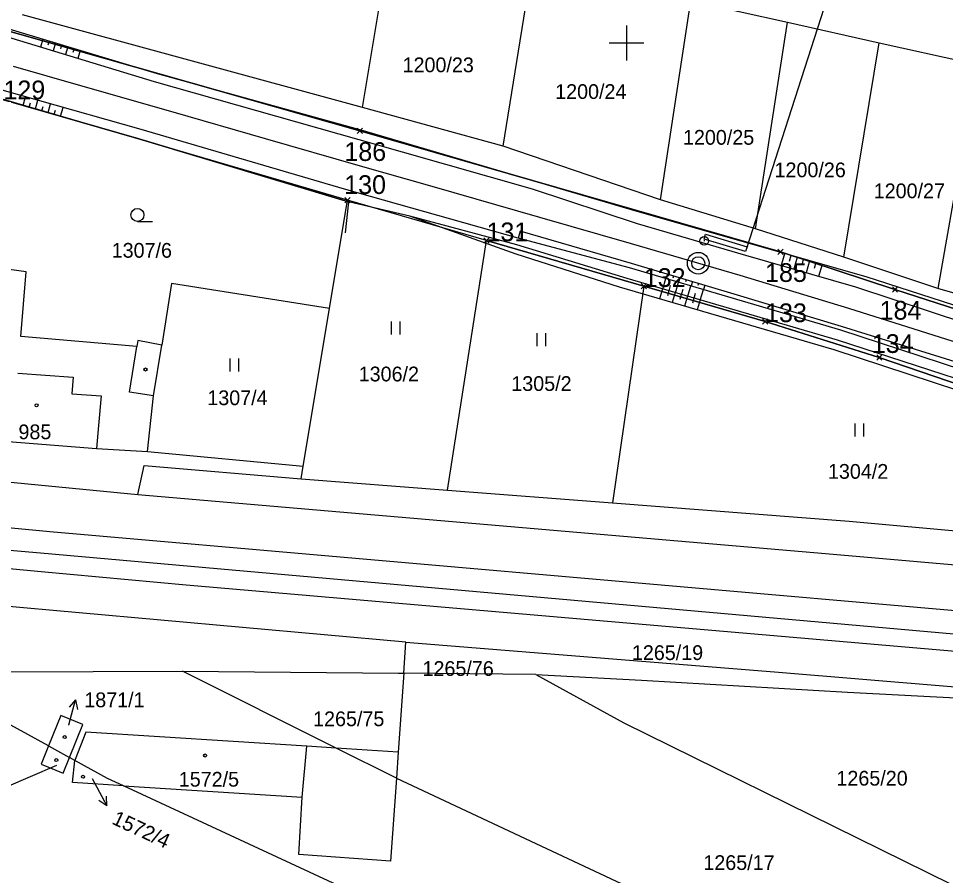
# Model space of a CAD drawing. Extents: x -779302 to -774398, y -1144902 to -1142831.
# Drawn here: x -777170.1 to -777063.2, y -1143896 to -1143797.2 of the extents above; entities that cross this region are included whole.
import ezdxf

# ---------------------------------------------------------------- set-up
doc = ezdxf.new("R2010")
doc.units = 0
for name, color, linetype in [('hektosit - Vrstva 5', 7, 'Continuous'), ('Hranice parcel', 7, 'Continuous'), ('legenda I_5_2 - Vrstva 53', 7, 'Continuous'), ('Parcelní čísla', 7, 'Continuous'), ('Pop  PČ popisy', 7, 'Continuous'), ('SŽDC', 7, 'Continuous'), ('Vnitřní kresba', 7, 'Continuous'), ('zjednodus_g_situ-seda - Vrstva 1', 7, 'Continuous'), ('zjednodus_g_situ-seda - Vrstva 17', 7, 'Continuous'), ('zjednodus_g_situ-seda - Vrstva 48', 7, 'Continuous'), ('zjednodus_g_situ-seda - Vrstva 49', 7, 'Continuous'), ('zjednodus_g_situ-seda - Vrstva 7', 7, 'Continuous'), ('zjednodus_g_situ-seda - Vrstva 9', 7, 'Continuous'), ('Značky budov', 7, 'Continuous'), ('Značky kultur', 7, 'Continuous')]:
    doc.layers.add(name, color=color, linetype=linetype)

msp = doc.modelspace()

# ---------------------------------------------------------------- linework, layer by layer
at = {"layer": 'hektosit - Vrstva 5'}
for p, q in [((-777100, -1143798), (-777100, -1143802)), ((-777102, -1143800), (-777098, -1143800))]:
    msp.add_line(p, q, dxfattribs=at)
at = {"layer": 'Hranice parcel'}
for p, q in [((-777130.46, -1143807.42), (-777127.12, -1143787.44)), ((-777114.23, -1143811.91), (-777110.85, -1143791.06)), ((-777096.09, -1143818.07), (-777092.58, -1143795.13)), ((-777092.58, -1143795.13), (-777081.42, -1143797.61)), ((-777130.46, -1143807.42), (-777169.67, -1143796.75)), ((-777085.1, -1143821.41), (-777081.42, -1143797.61)), ((-777081.42, -1143797.61), (-777070.84, -1143799.97)), ((-777074.92, -1143824.71), (-777070.84, -1143799.97)), ((-777070.84, -1143799.97), (-777059.57, -1143802.48)), ((-777059.57, -1143802.48), (-777064.09, -1143828.29)), ((-777132.17, -1143818.13), (-777171.85, -1143806.53)), ((-777114.23, -1143811.91), (-777130.46, -1143807.42)), ((-777096.09, -1143818.07), (-777114.23, -1143811.91)), ((-777134.26, -1143830.63), (-777132.17, -1143818.13)), ((-777116.14, -1143822.78), (-777132.17, -1143818.13)), ((-777085.1, -1143821.41), (-777096.09, -1143818.07)), ((-777074.92, -1143824.71), (-777085.1, -1143821.41)), ((-777120.64, -1143851.57), (-777116.14, -1143822.78)), ((-777116.14, -1143822.78), (-777098, -1143828.05)), ((-777064.09, -1143828.29), (-777074.92, -1143824.71)), ((-777098, -1143828.05), (-777101.59, -1143853.04)), ((-777053.74, -1143831.32), (-777064.09, -1143828.29)), ((-777137.29, -1143848.79), (-777134.26, -1143830.63)), ((-777155.25, -1143847.09), (-777137.29, -1143848.79)), ((-777137.5, -1143850.27), (-777137.29, -1143848.79)), ((-777137.5, -1143850.27), (-777120.64, -1143851.57)), ((-777120.64, -1143851.57), (-777101.59, -1143853.04)), ((-777125.43, -1143869.09), (-777184.32, -1143863.79)), ((-777125.68, -1143872.67), (-777125.43, -1143869.09)), ((-777125.43, -1143869.09), (-777124.98, -1143869.13)), ((-777151.21, -1143872.43), (-777126.28, -1143872.66)), ((-777126.28, -1143872.66), (-777125.68, -1143872.67)), ((-777110.44, -1143872.81), (-777125.68, -1143872.67)), ((-777166.67, -1143881.06), (-777164.25, -1143882.39)), ((-777163.6, -1143882.75), (-777164.25, -1143882.39))]:
    msp.add_line(p, q, dxfattribs=at)
for points in [[(-776969.85, -1143863.66), (-776987.47, -1143857.88), (-777014.89, -1143846.57), (-777042.6, -1143836.95), (-777069.03, -1143828.43), (-777082.24, -1143824.08), (-777130.76, -1143810.13), (-777274.26, -1143769.36), (-777322.71, -1143754.8), (-777354.97, -1143745.11)], [(-777153.6, -1143834.83), (-777156.35, -1143834.31), (-777156.46, -1143835), (-777169.83, -1143833.84), (-777169.25, -1143826.39), (-777171.18, -1143826.11), (-777174.72, -1143825.65)], [(-777134.26, -1143830.63), (-777152.46, -1143827.73), (-777153.6, -1143834.83)], [(-777098, -1143828.05), (-777084.01, -1143832.11), (-777070.84, -1143836.27), (-777043.81, -1143845.48)], [(-777313.47, -1143830.96), (-777307.07, -1143834.06), (-777294.79, -1143837.91), (-777291.06, -1143838.91), (-777215.44, -1143846.33), (-777156.34, -1143852.08), (-777155.61, -1143848.73), (-777137.5, -1143850.27)], [(-777155.25, -1143847.09), (-777154.55, -1143840.69), (-777153.6, -1143834.83)], [(-776998.39, -1143882.22), (-777014.02, -1143874.66), (-777035.36, -1143870.54), (-777167.58, -1143858.82), (-777281.88, -1143848.9), (-777289.53, -1143848.43), (-777292.27, -1143847.75), (-777303.16, -1143845.03)], [(-777177.16, -1143845.5), (-777161.12, -1143846.74), (-777155.25, -1143847.09)], [(-777101.59, -1143853.04), (-777074.31, -1143855.14), (-777045.91, -1143857.73)], [(-777211.92, -1143858.84), (-777211.13, -1143856.84), (-777167.5, -1143860.96), (-777150.77, -1143862.48), (-777035.76, -1143872.38), (-777017.82, -1143877.1)], [(-777124.98, -1143869.13), (-777082.45, -1143872.54), (-777032.92, -1143876.65)], [(-777166.67, -1143881.06), (-777182.17, -1143872.56), (-777151.21, -1143872.43)], [(-777126.53, -1143884.78), (-777133.48, -1143881.32), (-777151.21, -1143872.43)], [(-777125.68, -1143872.67), (-777126.32, -1143881.78), (-777126.53, -1143884.78)], [(-777110.44, -1143872.81), (-777100.29, -1143878.41), (-777041.02, -1143907.6)], [(-777110.44, -1143872.81), (-777098.28, -1143873.49), (-777074.51, -1143874.84), (-777060.56, -1143875.59), (-777043.14, -1143876.21)], [(-777164.25, -1143882.39), (-777162.69, -1143878.57), (-777165.23, -1143877.53), (-777166.67, -1143881.06)], [(-777158.02, -1143885.65), (-777137.41, -1143886.96), (-777136.87, -1143881.1), (-777162.34, -1143879.46), (-777163.59, -1143882.64), (-777163.6, -1143882.75)], [(-777166.67, -1143881.06), (-777167.52, -1143883.15), (-777164.98, -1143884.18), (-777164.25, -1143882.39)], [(-777158.02, -1143885.65), (-777163.88, -1143885.28), (-777163.6, -1143882.75)], [(-777158.02, -1143885.65), (-777159.84, -1143884.81), (-777163.6, -1143882.75)], [(-777126.53, -1143884.78), (-777059.22, -1143916.33), (-777057.27, -1143917.26)], [(-777064.63, -1143929.09), (-777108.64, -1143908.55), (-777158.02, -1143885.65)]]:
    msp.add_lwpolyline(points, dxfattribs=at)
at = {"layer": 'legenda I_5_2 - Vrstva 53'}
for points in [[(-777442.54, -1143720.48), (-777400.53, -1143733.41), (-777370.73, -1143741.3), (-777366.62, -1143741.88), (-777364.22, -1143742.54), (-777360.64, -1143743.54), (-777354.97, -1143745.11), (-777322.71, -1143754.8), (-777274.26, -1143769.36), (-777130.76, -1143810.13), (-777082.24, -1143824.08), (-777069.03, -1143828.43), (-777042.6, -1143836.95), (-777014.89, -1143846.57), (-776987.47, -1143857.88), (-776969.85, -1143863.66), (-776958.69, -1143867.83), (-776937.4, -1143878.07), (-776932.26, -1143880.54), (-776911.85, -1143884.6)], [(-776982.48, -1143870.69), (-777002.25, -1143861.05), (-777016.74, -1143855.53), (-777043.81, -1143845.48), (-777070.84, -1143836.27), (-777084.01, -1143832.11), (-777098, -1143828.05), (-777116.14, -1143822.78), (-777132.17, -1143818.13), (-777171.85, -1143806.53)]]:
    msp.add_lwpolyline(points, dxfattribs=at)
at = {"layer": 'Pop  PČ popisy'}
for p, q in [((-777164.31, -1143878.64), (-777163.53, -1143875.74)), ((-777163.53, -1143875.74), (-777164.28, -1143876.58)), ((-777163.53, -1143875.74), (-777163.31, -1143876.84)), ((-777164.32, -1143878.66), (-777164.31, -1143878.64)), ((-777165.75, -1143883.32), (-777168.78, -1143884.63)), ((-777168.78, -1143884.63), (-777171.54, -1143885.8)), ((-777161.62, -1143884.81), (-777161.34, -1143885.33)), ((-777161.34, -1143885.33), (-777159.93, -1143887.98)), ((-777159.93, -1143887.98), (-777159.96, -1143886.86)), ((-777159.93, -1143887.98), (-777160.84, -1143887.33))]:
    msp.add_line(p, q, dxfattribs=at)
at = {"layer": 'SŽDC'}
for p, q in [((-777130.56, -1143810.33), (-777131.06, -1143809.83)), ((-777130.56, -1143809.93), (-777131.06, -1143810.43)), ((-777130.96, -1143810.33), (-777130.46, -1143809.83)), ((-777130.96, -1143809.93), (-777130.46, -1143810.43)), ((-777130.76, -1143810.13), (-777130.76, -1143810.13)), ((-777131.97, -1143818.33), (-777132.47, -1143817.83)), ((-777131.97, -1143817.93), (-777132.47, -1143818.43)), ((-777132.37, -1143818.33), (-777131.87, -1143817.83)), ((-777132.37, -1143817.93), (-777131.87, -1143818.43)), ((-777132.17, -1143818.13), (-777132.17, -1143818.13)), ((-777115.94, -1143822.98), (-777116.44, -1143822.48)), ((-777115.94, -1143822.58), (-777116.44, -1143823.08)), ((-777116.34, -1143822.98), (-777115.84, -1143822.48)), ((-777116.34, -1143822.58), (-777115.84, -1143823.08)), ((-777116.14, -1143822.78), (-777116.14, -1143822.78)), ((-777082.04, -1143824.28), (-777082.54, -1143823.78)), ((-777082.04, -1143823.88), (-777082.54, -1143824.38)), ((-777082.44, -1143824.28), (-777081.94, -1143823.78)), ((-777082.44, -1143823.88), (-777081.94, -1143824.38)), ((-777082.24, -1143824.08), (-777082.24, -1143824.08)), ((-777097.8, -1143828.25), (-777098.3, -1143827.75)), ((-777097.8, -1143827.85), (-777098.3, -1143828.35)), ((-777098.2, -1143828.25), (-777097.7, -1143827.75)), ((-777098.2, -1143827.85), (-777097.7, -1143828.35)), ((-777098, -1143828.05), (-777098, -1143828.05)), ((-777068.83, -1143828.63), (-777069.33, -1143828.13)), ((-777068.83, -1143828.23), (-777069.33, -1143828.73)), ((-777069.23, -1143828.63), (-777068.73, -1143828.13)), ((-777069.23, -1143828.23), (-777068.73, -1143828.73)), ((-777069.03, -1143828.43), (-777069.03, -1143828.43)), ((-777083.81, -1143832.31), (-777084.31, -1143831.81)), ((-777083.81, -1143831.91), (-777084.31, -1143832.41)), ((-777084.21, -1143832.31), (-777083.71, -1143831.81)), ((-777084.21, -1143831.91), (-777083.71, -1143832.41)), ((-777084.01, -1143832.11), (-777084.01, -1143832.11)), ((-777070.64, -1143836.47), (-777071.14, -1143835.97)), ((-777071.04, -1143836.47), (-777070.54, -1143835.97)), ((-777070.64, -1143836.07), (-777071.14, -1143836.57)), ((-777071.04, -1143836.07), (-777070.54, -1143836.57)), ((-777070.84, -1143836.27), (-777070.84, -1143836.27))]:
    msp.add_line(p, q, dxfattribs=at)
for points in [[(-777442.54, -1143720.48), (-777400.53, -1143733.41), (-777370.73, -1143741.3), (-777366.62, -1143741.88), (-777364.22, -1143742.54), (-777360.64, -1143743.54), (-777354.97, -1143745.11), (-777322.71, -1143754.8), (-777274.26, -1143769.36), (-777130.76, -1143810.13), (-777082.24, -1143824.08), (-777069.03, -1143828.43), (-777042.6, -1143836.95), (-777014.89, -1143846.57), (-776987.47, -1143857.88), (-776969.85, -1143863.66), (-776958.69, -1143867.83), (-776937.4, -1143878.07), (-776932.26, -1143880.54), (-776911.85, -1143884.6)], [(-776982.48, -1143870.69), (-777002.25, -1143861.05), (-777016.74, -1143855.53), (-777043.81, -1143845.48), (-777070.84, -1143836.27), (-777084.01, -1143832.11), (-777098, -1143828.05), (-777116.14, -1143822.78), (-777132.17, -1143818.13), (-777171.85, -1143806.53)]]:
    msp.add_lwpolyline(points, dxfattribs=at)
at = {"layer": 'Vnitřní kresba'}
for p, q in [((-777157.31, -1143840.25), (-777156.46, -1143835)), ((-777170.21, -1143838.07), (-777163.81, -1143838.54)), ((-777163.81, -1143838.54), (-777163.95, -1143840.45)), ((-777154.55, -1143840.69), (-777157.31, -1143840.25)), ((-777163.95, -1143840.45), (-777160.6, -1143840.7)), ((-777160.6, -1143840.7), (-777160.89, -1143844.1)), ((-777160.89, -1143844.1), (-777161.12, -1143846.74)), ((-777166.52, -1143856.36), (-777216.02, -1143851.57)), ((-777156.34, -1143852.08), (-777077.05, -1143858.86)), ((-777051.48, -1143866.41), (-777166.52, -1143856.36)), ((-777077.05, -1143858.86), (-777046.53, -1143861.57)), ((-777133.48, -1143881.32), (-777136.87, -1143881.1)), ((-777126.32, -1143881.78), (-777133.48, -1143881.32)), ((-777126.53, -1143884.78), (-777127.2, -1143894.33)), ((-777137.77, -1143893.58), (-777137.41, -1143886.96)), ((-777127.2, -1143894.33), (-777137.77, -1143893.58))]:
    msp.add_line(p, q, dxfattribs=at)
at = {"layer": 'zjednodus_g_situ-seda - Vrstva 1'}
msp.add_line((-777122.39, -1143816.56), (-777130.69, -1143814.19), dxfattribs=at)
for points in [[(-777130.69, -1143814.19), (-777141.61, -1143811.05), (-777152.26, -1143807.98), (-777162.91, -1143804.93), (-777170.68, -1143802.7)], [(-776976.22, -1143866.7), (-776986.48, -1143862.49), (-776998.36, -1143857.65), (-777010.89, -1143852.7), (-777023.89, -1143847.77), (-777036.16, -1143843.3), (-777048.78, -1143838.91), (-777061.58, -1143834.66), (-777074.36, -1143830.6), (-777086.89, -1143826.8), (-777099.41, -1143823.17), (-777109.99, -1143820.13), (-777122.39, -1143816.56)]]:
    msp.add_lwpolyline(points, dxfattribs=at)
at = {"layer": 'zjednodus_g_situ-seda - Vrstva 17'}
msp.add_lwpolyline([(-777322.76, -1143775.41), (-777322, -1143767.74), (-777310.45, -1143770.73), (-777305.37, -1143768.47), (-777286.3, -1143773.57), (-777283.05, -1143774.46), (-777251.82, -1143783.01), (-777251.5, -1143783.39), (-777238, -1143787.23), (-777222.97, -1143791.59), (-777208.61, -1143795.68), (-777184.61, -1143802.73), (-777171.85, -1143806.54), (-777156.22, -1143811.05), (-777132.05, -1143818.32), (-777132.45, -1143821.9)], dxfattribs=at)
at = {"layer": 'zjednodus_g_situ-seda - Vrstva 48'}
for p, q in [((-777167.3, -1143799.57), (-777167.57, -1143800.47)), ((-777166.58, -1143799.79), (-777166.72, -1143800.24)), ((-777165.86, -1143800), (-777166.13, -1143800.91)), ((-777165.14, -1143800.22), (-777165.28, -1143800.67)), ((-777164.43, -1143800.44), (-777164.7, -1143801.34)), ((-777163.71, -1143800.65), (-777163.84, -1143801.11)), ((-777162.99, -1143800.87), (-777163.26, -1143801.78)), ((-777169.59, -1143807.19), (-777169.31, -1143806.2)), ((-777168.88, -1143807.4), (-777168.73, -1143806.9)), ((-777168.15, -1143807.61), (-777167.87, -1143806.61)), ((-777166.71, -1143808.02), (-777166.42, -1143807.02)), ((-777167.43, -1143807.82), (-777167.29, -1143807.31)), ((-777165.99, -1143808.23), (-777165.85, -1143807.73)), ((-777165.27, -1143808.44), (-777164.98, -1143807.42)), ((-777081.76, -1143824.3), (-777082.15, -1143825.67)), ((-777081.04, -1143824.5), (-777081.24, -1143825.19)), ((-777080.32, -1143824.71), (-777080.71, -1143826.09)), ((-777079.6, -1143824.92), (-777079.79, -1143825.6)), ((-777078.88, -1143825.12), (-777079.27, -1143826.5)), ((-777078.15, -1143825.33), (-777078.35, -1143826.02)), ((-777077.43, -1143825.54), (-777077.83, -1143826.92)), ((-777095.8, -1143828.37), (-777095.44, -1143827.17)), ((-777095.27, -1143826.65), (-777095.43, -1143827.17)), ((-777094.56, -1143826.87), (-777094.63, -1143827.13)), ((-777093.84, -1143827.08), (-777093.99, -1143827.6)), ((-777093.12, -1143827.3), (-777093.2, -1143827.55)), ((-777095.83, -1143828.36), (-777096.17, -1143829.5)), ((-777095.08, -1143828.58), (-777094.9, -1143827.98)), ((-777094.36, -1143828.79), (-777094, -1143827.59)), ((-777093.64, -1143829), (-777093.46, -1143828.4)), ((-777092.92, -1143829.21), (-777092.57, -1143828.02)), ((-777092.4, -1143827.51), (-777092.55, -1143828.02)), ((-777091.68, -1143827.73), (-777091.76, -1143827.98)), ((-777091.48, -1143829.64), (-777091.13, -1143828.44)), ((-777090.96, -1143827.94), (-777091.11, -1143828.44)), ((-777095.11, -1143828.57), (-777095.28, -1143829.14)), ((-777094.39, -1143828.78), (-777094.73, -1143829.92)), ((-777093.67, -1143828.99), (-777093.84, -1143829.56)), ((-777092.95, -1143829.2), (-777093.29, -1143830.35)), ((-777092.23, -1143829.41), (-777092.4, -1143829.99)), ((-777092.2, -1143829.42), (-777092.02, -1143828.83)), ((-777091.51, -1143829.63), (-777091.85, -1143830.77))]:
    msp.add_line(p, q, dxfattribs=at)
at = {"layer": 'zjednodus_g_situ-seda - Vrstva 49'}
for p, q in [((-777112.25, -1143821.71), (-777112.49, -1143822.49)), ((-777099.42, -1143825.41), (-777112.25, -1143821.71))]:
    msp.add_line(p, q, dxfattribs=at)
for points in [[(-777098.75, -1143819.43), (-777110.63, -1143815.95), (-777130.58, -1143810.07), (-777154.09, -1143803.54), (-777178.48, -1143796.22), (-777203.84, -1143789.11), (-777228.58, -1143782.14), (-777253.24, -1143774.92), (-777282.35, -1143766.11), (-777304.96, -1143759.88), (-777318.88, -1143756.19), (-777338.5, -1143750.54), (-777354.58, -1143745.16), (-777354.96, -1143741.88)], [(-777098.73, -1143820.87), (-777110.83, -1143816.86), (-777130.82, -1143811.15), (-777154.42, -1143804.46), (-777178.83, -1143797.06), (-777204.32, -1143789.84), (-777229.03, -1143782.93), (-777253.44, -1143775.85), (-777282.18, -1143767.44), (-777305.37, -1143760.99), (-777319.23, -1143756.71), (-777338.44, -1143751.41), (-777355.48, -1143746.06)], [(-777099.65, -1143825.93), (-777112.49, -1143822.49), (-777132.51, -1143816.84), (-777155.96, -1143809.96), (-777179.91, -1143803.22), (-777205.91, -1143795.37), (-777230.52, -1143788.45), (-777254.65, -1143781.47), (-777282.78, -1143773.56), (-777283.05, -1143774.46)], [(-777099.93, -1143827.15), (-777112.65, -1143823.28), (-777124.98, -1143819.98), (-777132.05, -1143818.32), (-777156.22, -1143811.05), (-777171.85, -1143806.54), (-777184.61, -1143802.73), (-777208.61, -1143795.68), (-777222.97, -1143791.59), (-777238, -1143787.23), (-777251.5, -1143783.39), (-777251.82, -1143783.01), (-777283.05, -1143774.46)], [(-776968.2, -1143850.12), (-776971, -1143856.57), (-776973.89, -1143861.01), (-776975.92, -1143862.12), (-776984.87, -1143858.78), (-776998.01, -1143853.19), (-777022.63, -1143844.17), (-777047.12, -1143835.12), (-777072.37, -1143826.98), (-777098.75, -1143819.43)], [(-777100.79, -1143828.15), (-777112.71, -1143824.35), (-777124.98, -1143819.98)], [(-776966.65, -1143850.49), (-776969.22, -1143857.63), (-776972.42, -1143862.97), (-776975.34, -1143863.74), (-776985.5, -1143860.23), (-776998.08, -1143854.94), (-777010.13, -1143850.49), (-777022.9, -1143845.63), (-777035.32, -1143841.2), (-777047.81, -1143836.56), (-777060.73, -1143832.38), (-777073.56, -1143828.16), (-777086.22, -1143824.49), (-777098.73, -1143820.87)], [(-776980.63, -1143868.51), (-776987.69, -1143864.9), (-777000.82, -1143859.37), (-777024.99, -1143850.09), (-777049.61, -1143841.54), (-777075.28, -1143833.11), (-777099.65, -1143825.93)], [(-776978.42, -1143868.82), (-776979.3, -1143867.74), (-776981.14, -1143867.1), (-776987.23, -1143864.35), (-776999, -1143859.53), (-777012.06, -1143854.5), (-777024.82, -1143849.55), (-777036.88, -1143845.23), (-777049.2, -1143840.92), (-777062.08, -1143836.76), (-777075.18, -1143832.7), (-777087.57, -1143828.95), (-777099.42, -1143825.41)], [(-776986.6, -1143868.85), (-776984.15, -1143868.31), (-776988.42, -1143865.74), (-777001.36, -1143860.61), (-777025.6, -1143851.38), (-777049.86, -1143842.63), (-777075.67, -1143834.28), (-777099.93, -1143827.15)], [(-777025.6, -1143851.38), (-777050.33, -1143843.82), (-777076.04, -1143835.4), (-777100.79, -1143828.15)]]:
    msp.add_lwpolyline(points, dxfattribs=at)
at = {"layer": 'zjednodus_g_situ-seda - Vrstva 7'}
msp.add_line((-777090.97, -1143822.82), (-777091.07, -1143822.8), dxfattribs=at)
for centre, radius in [((-777091.02, -1143822.81), 0.5), ((-777091.72, -1143825.4), 1.25), ((-777091.72, -1143825.4), 0.752)]:
    msp.add_circle(centre, radius, dxfattribs=at)
at = {"layer": 'zjednodus_g_situ-seda - Vrstva 9'}
msp.add_line((-777086.17, -1143823.78), (-777067.91, -1143767.04), dxfattribs=at)
msp.add_lwpolyline([(-777085.91, -1143822.91), (-777086.08, -1143823.49), (-777086.25, -1143824.06), (-777091.04, -1143822.62), (-777090.87, -1143822.05), (-777086.08, -1143823.49)], dxfattribs=at)
at = {"layer": 'Značky budov'}
for centre in [(-777155.47, -1143837.65), (-777168.03, -1143841.78), (-777164.79, -1143880.04), (-777165.76, -1143882.69), (-777148.59, -1143882.16), (-777162.67, -1143884.61)]:
    msp.add_circle(centre, 0.175, dxfattribs=at)
at = {"layer": 'Značky kultur'}
for p, q in [((-777156.4, -1143820.58), (-777154.65, -1143820.58)), ((-777127.09, -1143833.6), (-777127.09, -1143832.1)), ((-777126.09, -1143833.6), (-777126.09, -1143832.1)), ((-777110.3, -1143834.95), (-777110.3, -1143833.45)), ((-777109.3, -1143834.95), (-777109.3, -1143833.45)), ((-777145.72, -1143837.87), (-777145.72, -1143836.37)), ((-777144.72, -1143837.87), (-777144.72, -1143836.37)), ((-777073.62, -1143845.38), (-777073.62, -1143843.88)), ((-777072.62, -1143845.38), (-777072.62, -1143843.88))]:
    msp.add_line(p, q, dxfattribs=at)
msp.add_circle((-777156.4, -1143819.83), 0.75, dxfattribs=at)

# ---------------------------------------------------------------- texts
at = {"layer": 'Parcelní čísla'}
for s, p in [('1200/23', (-777125.82, -1143803.37)), ('1200/24', (-777108.22, -1143806.45)), ('1200/25', (-777093.48, -1143811.73)), ('1200/26', (-777082.92, -1143815.48)), ('1200/27', (-777071.48, -1143817.9)), ('1307/6', (-777159.37, -1143824.76)), ('1306/2', (-777130.88, -1143839.02)), ('1305/2', (-777113.28, -1143840.12)), ('1307/4', (-777148.34, -1143841.76)), ('985', (-777170.12, -1143845.69)), ('1304/2', (-777076.76, -1143850.25)), ('1265/19', (-777099.37, -1143871.15)), ('1265/76', (-777123.52, -1143872.98)), ('1871/1', (-777162.53, -1143876.59)), ('1265/75', (-777136.14, -1143878.78)), ('1572/5', (-777151.63, -1143885.75)), ('1265/20', (-777075.78, -1143885.63)), ('1265/17', (-777091.13, -1143895.36))]:
    msp.add_text(s, height=1.7, dxfattribs=at).set_placement(p)
msp.add_text('1572/4', height=1.7, rotation=335, dxfattribs=at).set_placement((-777159.46, -1143889.99))
at = {"layer": 'SŽDC'}
for s, p in [('129', (-777171.85, -1143806.49)), ('186', (-777132.53, -1143813.6)), ('130', (-777132.55, -1143817.41)), ('131', (-777116.14, -1143822.86)), ('132', (-777098, -1143828.13)), ('185', (-777084.01, -1143827.55)), ('133', (-777084.01, -1143832.19)), ('184', (-777070.8, -1143831.9)), ('134', (-777071.7, -1143835.74))]:
    msp.add_text(s, height=2.16, dxfattribs=at).set_placement(p)

doc.saveas('drawing.dxf')
